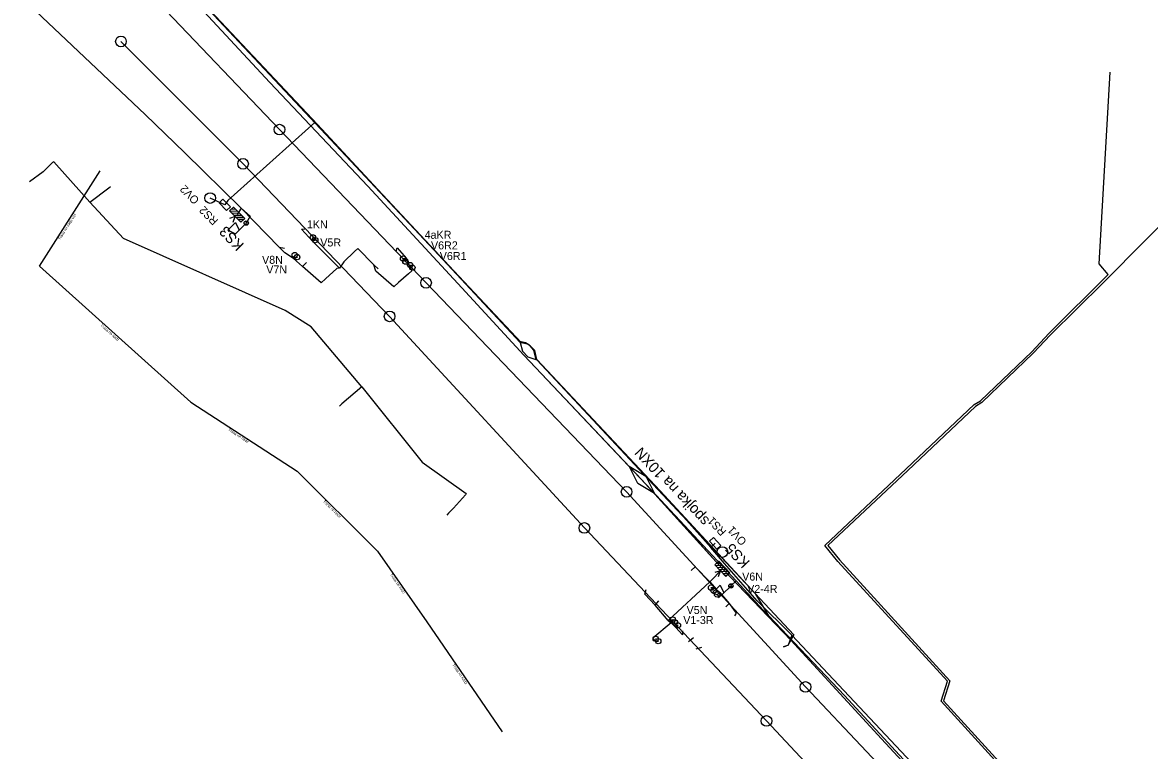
# Model space of a CAD drawing. Extents: x -748507 to -687366, y -1057342 to -1024924.
# Drawn here: x -744934.9 to -744723.6, y -1030468.1 to -1030331.7 of the extents above; entities that cross this region are included whole.
import ezdxf

# ---------------------------------------------------------------- set-up
doc = ezdxf.new("R2010")
doc.units = 0
for name, color, linetype in [('6kV - SŽDC', 7, 'Continuous'), ('DK + TKK - SŽDC', 7, 'Continuous'), ('kanalizace ČD', 7, 'Continuous'), ('Sděl MK - SŽDC', 7, 'Continuous'), ('Telefonica O2', 7, 'Continuous'), ('TK+DOK_Pha Holešovice - Kralupy', 7, 'Continuous'), ('Vedení NN - SŽDC', 7, 'Continuous'), ('ČEZ Distribuce - NN', 7, 'Continuous'), ('ČEZ Distribuce - VN', 7, 'Continuous')]:
    doc.layers.add(name, color=color, linetype=linetype)

msp = doc.modelspace()

# ---------------------------------------------------------------- linework, layer by layer
at = {"layer": '6kV - SŽDC'}
for points in [[(-744879.58, -1030350.79), (-744903.77, -1030325.05), (-744907.55, -1030322.07), (-744910.63, -1030318.43), (-744916.73, -1030311.64), (-744931.93, -1030295.39), (-744935.74, -1030288.25), (-744945.13, -1030279.35), (-744951.72, -1030273.28)], [(-744841.33, -1030391.71), (-744852.16, -1030380.21), (-744865.84, -1030365.61), (-744879.58, -1030350.79)], [(-744780.79, -1030457.84), (-744794.99, -1030442.91), (-744797.4, -1030438.85), (-744815.34, -1030419.47), (-744838.45, -1030394.84), (-744838.84, -1030393.14), (-744839.94, -1030392), (-744841.33, -1030391.71), (-744852.16, -1030380.21), (-744865.84, -1030365.61)], [(-744633.68, -1030663.87), (-744637.13, -1030652.92), (-744643.81, -1030639.98), (-744654.57, -1030618.88), (-744661.52, -1030605.24), (-744678.82, -1030577.15), (-744684.35, -1030569.37), (-744699.32, -1030549.46), (-744712.76, -1030532.27), (-744717.68, -1030530.39), (-744726.6, -1030520.87), (-744725.03, -1030517.65), (-744732.67, -1030510.12), (-744740.81, -1030500.54), (-744748.56, -1030491.47), (-744763.12, -1030477.01), (-744780.79, -1030457.84)]]:
    msp.add_lwpolyline(points, dxfattribs=at)
at = {"layer": 'DK + TKK - SŽDC'}
for p, q in [((-744894.92, -1030366.69), (-744895.77, -1030366.68)), ((-744895.29, -1030366.31), (-744895.39, -1030366.31)), ((-744894.55, -1030367.07), (-744895.97, -1030367.05)), ((-744894.18, -1030367.45), (-744895.59, -1030367.43)), ((-744893.81, -1030367.82), (-744895.22, -1030367.81)), ((-744893.44, -1030368.2), (-744894.85, -1030368.19)), ((-744893.42, -1030368.58), (-744894.48, -1030368.57)), ((-744893.8, -1030368.95), (-744894.11, -1030368.95)), ((-744880.49, -1030371.95), (-744880.39, -1030371.95)), ((-744880.06, -1030372.46), (-744879.96, -1030372.46)), ((-744883.91, -1030375.25), (-744883.81, -1030375.25)), ((-744883.45, -1030375.64), (-744883.35, -1030375.64)), ((-744863.6, -1030375.93), (-744863.5, -1030375.93)), ((-744863.15, -1030376.47), (-744863.05, -1030376.47)), ((-744862.27, -1030377.12), (-744862.17, -1030377.12)), ((-744861.85, -1030377.6), (-744861.75, -1030377.6)), ((-744803.57, -1030433.49), (-744804.98, -1030433.44)), ((-744803.93, -1030433.1), (-744804.78, -1030433.08)), ((-744803.2, -1030433.88), (-744804.62, -1030433.83)), ((-744804.3, -1030432.71), (-744804.39, -1030432.71)), ((-744802.84, -1030434.26), (-744804.26, -1030434.22)), ((-744802.48, -1030434.65), (-744803.89, -1030434.6)), ((-744802.47, -1030435.02), (-744803.53, -1030434.99)), ((-744802.86, -1030435.39), (-744803.17, -1030435.38)), ((-744805.86, -1030437.6), (-744805.76, -1030437.6)), ((-744805.37, -1030438.19), (-744805.27, -1030438.19)), ((-744804.74, -1030438.88), (-744804.64, -1030438.88)), ((-744813.03, -1030443.59), (-744812.93, -1030443.59)), ((-744812.63, -1030444.12), (-744812.53, -1030444.12)), ((-744812.06, -1030444.67), (-744811.96, -1030444.67)), ((-744816.22, -1030447.2), (-744816.12, -1030447.2)), ((-744815.75, -1030447.65), (-744815.65, -1030447.65))]:
    msp.add_line(p, q, dxfattribs=at)
for points in [[(-744893.96, -1030369.1), (-744896.06, -1030366.96), (-744895.34, -1030366.26), (-744893.24, -1030368.4)], [(-744803.02, -1030435.54), (-744805.07, -1030433.35), (-744804.34, -1030432.66), (-744802.29, -1030434.85)]]:
    msp.add_lwpolyline(points, close=True, dxfattribs=at)
for points in [[(-744893.96, -1030369.1), (-744896.06, -1030366.96), (-744895.34, -1030366.26), (-744893.24, -1030368.4), (-744893.96, -1030369.1)], [(-744893.87, -1030366.46), (-744894.65, -1030367.68)], [(-744886.78, -1030373.75), (-744893.87, -1030366.46)], [(-744895.37, -1030369.09), (-744895.01, -1030368.03), (-744896.07, -1030368.37)], [(-744882.61, -1030370.38), (-744881.98, -1030370.34)], [(-744880.53, -1030372.64), (-744882.61, -1030370.38)], [(-744880.01, -1030372.46), (-744880.53, -1030372.64), (-744880.44, -1030371.95)], [(-744875.45, -1030377.7), (-744880.53, -1030372.64)], [(-744886.78, -1030373.75), (-744885.75, -1030373.96)], [(-744878.89, -1030380.49), (-744882.41, -1030377.37), (-744884.08, -1030375.89), (-744885.71, -1030374.83), (-744886.78, -1030373.75)], [(-744869.05, -1030377.07), (-744872.05, -1030374.01), (-744872.64, -1030374.61), (-744874.66, -1030376.51), (-744875.45, -1030377.7), (-744875.98, -1030377.79)], [(-744864.81, -1030374.52), (-744864.68, -1030373.89), (-744862.93, -1030375.91)], [(-744883.86, -1030375.25), (-744884.08, -1030375.89), (-744883.4, -1030375.64)], [(-744882.41, -1030377.37), (-744881.64, -1030376.62)], [(-744869.05, -1030377.07), (-744868.24, -1030377.81)], [(-744862.3, -1030377.61), (-744861.93, -1030378.19), (-744862.55, -1030378.75), (-744864.39, -1030380.38), (-744865.3, -1030381.23), (-744868.68, -1030378.27), (-744869.05, -1030377.07)], [(-744863.55, -1030375.93), (-744862.93, -1030375.91), (-744863.1, -1030376.47)], [(-744862.93, -1030375.91), (-744862.3, -1030377.61)], [(-744862.22, -1030377.12), (-744862.3, -1030377.61), (-744861.8, -1030377.6)], [(-744875.98, -1030377.79), (-744878.11, -1030379.72), (-744878.89, -1030380.49)], [(-744748.99, -1030494.59), (-744753.74, -1030487.7), (-744773.86, -1030465.97), (-744790.82, -1030447.45), (-744803.68, -1030434.1), (-744816.94, -1030419.31)], [(-744803.68, -1030434.1), (-744806.02, -1030436.49), (-744813.84, -1030443.76)], [(-744809.56, -1030434.4), (-744808.81, -1030433.72)], [(-744806.02, -1030436.49), (-744808.81, -1030433.72)], [(-744803.02, -1030435.54), (-744805.07, -1030433.35), (-744804.34, -1030432.66), (-744802.29, -1030434.85), (-744803.02, -1030435.54)], [(-744804.43, -1030435.49), (-744804.04, -1030434.44), (-744805.12, -1030434.76)], [(-744818.19, -1030438.82), (-744817.94, -1030437.97)], [(-744806.02, -1030436.49), (-744805.25, -1030437.44), (-744804.83, -1030437.87), (-744804.17, -1030438.54), (-744802.44, -1030440.6)], [(-744805.81, -1030437.6), (-744805.25, -1030437.44)], [(-744805.32, -1030438.19), (-744804.83, -1030437.87)], [(-744804.69, -1030438.88), (-744804.17, -1030438.54)], [(-744816.29, -1030440.89), (-744818.19, -1030438.82)], [(-744816.29, -1030440.89), (-744815.62, -1030440.11)], [(-744802.44, -1030440.6), (-744803.05, -1030441.21)], [(-744802.44, -1030440.6), (-744801.07, -1030442.38), (-744801.4, -1030442.91)], [(-744813.84, -1030443.76), (-744816.29, -1030440.89)], [(-744813.28, -1030444.21), (-744816.75, -1030447.07)], [(-744813.84, -1030443.76), (-744813.28, -1030444.21), (-744812.94, -1030444.53), (-744812.4, -1030445.06), (-744811.16, -1030446.46)], [(-744812.98, -1030443.59), (-744813.28, -1030444.21)], [(-744812.94, -1030444.53), (-744812.58, -1030444.12)], [(-744812.4, -1030445.06), (-744812.01, -1030444.67)], [(-744811.15, -1030445.72), (-744811.16, -1030446.46)], [(-744810.01, -1030447.71), (-744809.11, -1030446.95)], [(-744816.75, -1030447.07), (-744816.21, -1030447.63)], [(-744816.17, -1030447.2), (-744816.21, -1030447.63), (-744815.7, -1030447.65)], [(-744808.58, -1030449.07), (-744807.51, -1030448.75)]]:
    msp.add_lwpolyline(points, dxfattribs=at)
for centre in [(-744880.44, -1030371.95), (-744880.01, -1030372.46), (-744883.86, -1030375.25), (-744883.4, -1030375.64), (-744863.55, -1030375.93), (-744863.1, -1030376.47), (-744862.22, -1030377.12), (-744861.8, -1030377.6), (-744805.81, -1030437.6), (-744805.32, -1030438.19), (-744804.69, -1030438.88), (-744812.98, -1030443.59), (-744812.58, -1030444.12), (-744812.01, -1030444.67), (-744816.17, -1030447.2), (-744815.7, -1030447.65)]:
    msp.add_circle(centre, 0.5, dxfattribs=at)
at = {"layer": 'kanalizace ČD'}
for points in [[(-744720.03, -1030529.66), (-744753.81, -1030492.57), (-744788.1, -1030456.23), (-744821.63, -1030419.65), (-744859.24, -1030380.47), (-744886.71, -1030351.73), (-744909.28, -1030328.12)], [(-744727.07, -1030535.84), (-744761.14, -1030499.23), (-744795.4, -1030462.6), (-744829.56, -1030426.42), (-744866.07, -1030386.75), (-744893.54, -1030358.16), (-744916.43, -1030335.2)]]:
    msp.add_lwpolyline(points, dxfattribs=at)
for centre in [(-744916.43, -1030335.2), (-744886.71, -1030351.73), (-744893.54, -1030358.16), (-744859.24, -1030380.47), (-744866.07, -1030386.75), (-744821.63, -1030419.65), (-744829.56, -1030426.42), (-744788.1, -1030456.23), (-744795.4, -1030462.6)]:
    msp.add_circle(centre, 1, dxfattribs=at)
at = {"layer": 'Sděl MK - SŽDC'}
for p, q in [((-744896.41, -1030370.58), (-744894.98, -1030369.18)), ((-744895, -1030371.3), (-744896.41, -1030370.58)), ((-744895.21, -1030371.51), (-744893.22, -1030369.55)), ((-744894.98, -1030369.18), (-744894.29, -1030370.6)), ((-744892.6, -1030369.45), (-744893.3, -1030369.44)), ((-744892.61, -1030369.05), (-744893.29, -1030369.04)), ((-744805.56, -1030438.54), (-744804.11, -1030437.16)), ((-744804.17, -1030439.29), (-744805.56, -1030438.54)), ((-744804.39, -1030439.49), (-744802.35, -1030437.57)), ((-744804.11, -1030437.16), (-744803.44, -1030438.6)), ((-744801.74, -1030437.48), (-744802.43, -1030437.46)), ((-744801.73, -1030437.08), (-744802.42, -1030437.06))]:
    msp.add_line(p, q, dxfattribs=at)
for points in [[(-744802.08, -1030437.28), (-744801.07, -1030436.31), (-744816.94, -1030419.31), (-744840.92, -1030394.05), (-744852.51, -1030381.42), (-744870.15, -1030362.35), (-744888.54, -1030342.9), (-744910.79, -1030318.89), (-744926.63, -1030301.78), (-744936.98, -1030290.45), (-744936.16, -1030290.05)], [(-744773.86, -1030465.97), (-744790.82, -1030447.45), (-744801.07, -1030436.31), (-744816.94, -1030419.31), (-744840.92, -1030394.05), (-744852.51, -1030381.42), (-744870.15, -1030362.35), (-744888.54, -1030342.9), (-744910.79, -1030318.89), (-744926.63, -1030301.78), (-744936.98, -1030290.45)], [(-744948.01, -1030316.74), (-744933.5, -1030328.45), (-744911.92, -1030348.93), (-744904.45, -1030356.11), (-744893.87, -1030366.46), (-744892.21, -1030367.96), (-744892.95, -1030369.25)], [(-744748.9, -1030495.91), (-744747.97, -1030495.07), (-744748.99, -1030494.59), (-744753.74, -1030487.7), (-744773.86, -1030465.97), (-744790.82, -1030447.45), (-744801.07, -1030436.31)]]:
    msp.add_lwpolyline(points, dxfattribs=at)
for centre in [(-744892.95, -1030369.25), (-744892.95, -1030369.25), (-744802.08, -1030437.28), (-744802.08, -1030437.28)]:
    msp.add_circle(centre, 0.401, dxfattribs=at)
at = {"layer": 'Telefonica O2'}
for points in [[(-744922.28, -1030365.33), (-744929.01, -1030357.78), (-744929.25, -1030357.92), (-744931.03, -1030359.63), (-744933.61, -1030361.54)], [(-744929.25, -1030357.92), (-744931.03, -1030359.63)], [(-744922.28, -1030365.33), (-744918.73, -1030362.64), (-744918.41, -1030362.41)], [(-744871.3, -1030399.93), (-744880.79, -1030388.73), (-744885.62, -1030385.66), (-744915.93, -1030372.17), (-744922.28, -1030365.33)], [(-744871.3, -1030399.93), (-744875.01, -1030403.14), (-744875.49, -1030403.59)], [(-744871.3, -1030399.93), (-744859.98, -1030414.09), (-744851.72, -1030419.93), (-744851.83, -1030420.18), (-744854.09, -1030422.7), (-744855.03, -1030423.65), (-744855.37, -1030424.02)]]:
    msp.add_lwpolyline(points, dxfattribs=at)
at = {"layer": 'TK+DOK_Pha Holešovice - Kralupy'}
for points in [[(-744818.78, -1030417.38), (-744840.92, -1030394.05), (-744852.51, -1030381.42), (-744870.15, -1030362.35), (-744888.54, -1030342.9), (-744910.79, -1030318.89), (-744926.63, -1030301.78), (-744936.98, -1030290.45), (-744940.24, -1030286.84), (-744944.31, -1030280.12), (-744947.52, -1030276.9), (-744950.99, -1030273.46), (-744961.24, -1030263.31), (-744962.68, -1030262.14), (-744967.88, -1030268.59)], [(-744753.74, -1030487.7), (-744773.86, -1030465.97), (-744790.82, -1030447.45), (-744803.68, -1030434.1), (-744818.78, -1030417.38), (-744840.92, -1030394.05), (-744852.51, -1030381.42), (-744870.15, -1030362.35), (-744888.54, -1030342.9), (-744910.79, -1030318.89), (-744926.63, -1030301.78), (-744936.98, -1030290.45), (-744940.24, -1030286.84), (-744944.31, -1030280.12), (-744947.52, -1030276.9), (-744950.99, -1030273.46), (-744962.68, -1030262.14)], [(-744816.4, -1030419.94), (-744819.51, -1030418.06), (-744821.15, -1030414.81), (-744818.04, -1030416.7), (-744816.4, -1030419.94)], [(-744698.44, -1030550.34), (-744711.31, -1030534.03), (-744714.87, -1030531.58), (-744719.2, -1030529.45), (-744720.98, -1030528.16), (-744731.45, -1030516.46), (-744735.86, -1030511.44), (-744745.28, -1030500.97), (-744746.7, -1030497.92), (-744747.25, -1030497.14), (-744748.99, -1030494.59), (-744753.74, -1030487.7), (-744773.86, -1030465.97), (-744790.82, -1030447.45), (-744803.68, -1030434.1), (-744818.78, -1030417.38)]]:
    msp.add_lwpolyline(points, dxfattribs=at)
at = {"layer": 'Vedení NN - SŽDC'}
for points in [[(-744880.08, -1030350.42), (-744904.13, -1030324.64), (-744910.5, -1030318.42), (-744909.6, -1030318.26), (-744902.75, -1030316.71), (-744898.23, -1030312.68), (-744897.84, -1030312.08), (-744897.24, -1030311.97)], [(-744900.02, -1030329.24), (-744875.2, -1030355.68), (-744857.8, -1030374.3), (-744841.57, -1030391.66), (-744841.14, -1030393.29), (-744840.15, -1030394.34), (-744838.49, -1030394.92), (-744816.66, -1030418.24), (-744790.26, -1030446.45), (-744791.39, -1030448.47), (-744792.28, -1030448.71)], [(-744805.87, -1030430.08), (-744813.49, -1030421.52), (-744838.65, -1030394.66), (-744839, -1030393.07), (-744839.7, -1030392.28), (-744840.57, -1030391.73), (-744841.67, -1030391.43), (-744867.35, -1030363.95), (-744880.08, -1030350.42), (-744896.37, -1030365.05), (-744896.97, -1030365.82), (-744899.71, -1030364.57)], [(-744895.91, -1030366.19), (-744896.63, -1030366.88), (-744898.03, -1030365.46), (-744897.31, -1030364.76), (-744895.91, -1030366.19)], [(-744804, -1030429.69), (-744804.73, -1030430.37), (-744806.1, -1030428.91), (-744805.37, -1030428.23), (-744804, -1030429.69)], [(-744797.13, -1030440.06), (-744803.28, -1030433.1), (-744805.87, -1030430.08), (-744805.05, -1030429.3)], [(-744725.07, -1030520.85), (-744725.31, -1030519.93), (-744724.91, -1030517.17), (-744728.77, -1030512.84), (-744733.05, -1030509.33), (-744734.32, -1030505.59), (-744738.8, -1030500.14), (-744740.4, -1030500.49), (-744744.93, -1030495.31), (-744745.57, -1030494.96), (-744746.28, -1030494.51), (-744750.68, -1030489.05), (-744790.65, -1030446.49), (-744797.13, -1030440.06)], [(-744790.65, -1030446.49), (-744791.35, -1030448.38), (-744792.23, -1030448.74)]]:
    msp.add_lwpolyline(points, dxfattribs=at)
for centre in [(-744899.71, -1030364.57), (-744803.69, -1030430.94)]:
    msp.add_circle(centre, 1, dxfattribs=at)
at = {"layer": 'ČEZ Distribuce - NN'}
for points in [[(-744931.72, -1030377.36), (-744920.33, -1030359.46)], [(-744931.72, -1030377.36), (-744903.34, -1030402.85)], [(-744903.34, -1030402.85), (-744883.43, -1030415.74)], [(-744883.43, -1030415.74), (-744868.32, -1030430.77)], [(-744868.32, -1030430.77), (-744859.06, -1030444.02)], [(-744859.06, -1030444.02), (-744844.99, -1030464.66)]]:
    msp.add_lwpolyline(points, dxfattribs=at)
at = {"layer": 'ČEZ Distribuce - VN'}
for points in [[(-744746.92, -1030476.22), (-744762.67, -1030458.92), (-744761.46, -1030455.17), (-744782.03, -1030432.68), (-744784.45, -1030429.68), (-744769.2, -1030415.33), (-744756.48, -1030403.3), (-744755.28, -1030402.57), (-744745.67, -1030393.38), (-744742.46, -1030389.94), (-744731.34, -1030378.91), (-744733.02, -1030376.87), (-744730.97, -1030340.95)], [(-744713.1, -1030358.6), (-744716.26, -1030364.3), (-744732.32, -1030380.44), (-744742.17, -1030390.22), (-744745.39, -1030393.66), (-744755.04, -1030402.89), (-744756.24, -1030403.62), (-744768.93, -1030415.62), (-744783.91, -1030429.72), (-744781.73, -1030432.42), (-744761.01, -1030455.07), (-744762.22, -1030458.82), (-744746.62, -1030475.95), (-744731.39, -1030492.65), (-744731.65, -1030494.03), (-744729.51, -1030500.91), (-744730.53, -1030504.13), (-744725.22, -1030508.07), (-744725.27, -1030508.34), (-744662.32, -1030599.61)]]:
    msp.add_lwpolyline(points, dxfattribs=at)

# ---------------------------------------------------------------- texts
at = {"layer": 'DK + TKK - SŽDC'}
for s, p in [('1KN', (-744881.57, -1030370.25)), ('4aKR', (-744859.5, -1030372.2)), ('V5R', (-744879.07, -1030373.64)), ('V6R2', (-744858.31, -1030374.19)), ('V6R1', (-744856.67, -1030376.18)), ('V8N', (-744889.98, -1030376.9)), ('V7N', (-744889.19, -1030378.71)), ('V6N', (-744799.97, -1030436.28)), ('V2-4R', (-744799.04, -1030438.6)), ('V5N', (-744810.39, -1030442.55)), ('V1-3R', (-744811.02, -1030444.43))]:
    msp.add_text(s, height=1.5, dxfattribs=at).set_placement(p)
for s, rotation, p in [('KS3', 134.3881, (-744893.23, -1030373.26)), ('KS5', 133.2147, (-744798.41, -1030432.78))]:
    msp.add_text(s, height=2, rotation=rotation, dxfattribs=at).set_placement(p)
at = {"layer": 'TK+DOK_Pha Holešovice - Kralupy'}
msp.add_text('spojka na 10XN', height=2, rotation=132.791, dxfattribs=at).set_placement((-744806, -1030424.95))
at = {"layer": 'Vedení NN - SŽDC'}
for s, rotation, p in [('OV2', 134.3881, (-744901.64, -1030364.85)), ('RS2', 134.3881, (-744898.1, -1030368.75)), ('RS1', 133.0947, (-744802.83, -1030427.03)), ('OV1', 133.0947, (-744799.02, -1030428.86))]:
    msp.add_text(s, height=1.5, rotation=rotation, dxfattribs=at).set_placement(p)
at = {"layer": 'ČEZ Distribuce - NN'}
for s, rotation, p in [('Trasa nn nadz izol', 57.5129, (-744927.84, -1030372.46)), ('Trasa nn nadz', 318.0689, (-744920.31, -1030388.49)), ('Trasa nn nadz', 327.0868, (-744896.38, -1030408.13)), ('Trasa nn nadz', 315.1559, (-744878.57, -1030421.49)), ('Trasa nn nadz', 304.9337, (-744866.03, -1030435.19)), ('Trasa nn nadz', 304.2919, (-744854.34, -1030452.11))]:
    msp.add_text(s, height=0.5, rotation=rotation, dxfattribs=at).set_placement(p)

doc.saveas('drawing.dxf')
